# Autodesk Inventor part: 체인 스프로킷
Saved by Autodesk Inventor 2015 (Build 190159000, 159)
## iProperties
Created: 2026-07
Part Number: 체인 스프로킷
Material: 일반
Document SubType Name: Modeling
Designer: USER
Density: 1 g/cm^3
Appearance: 기본값
Author: USER
Author: jhkim
Creation Date: 2026-07-01
Sending System: Autodesk Inventor 2027
Preprocessor: ST-DEVELOPER v20.1
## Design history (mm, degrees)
node "체인 스프로킷1"
body "Solid1"
node "기준1"
